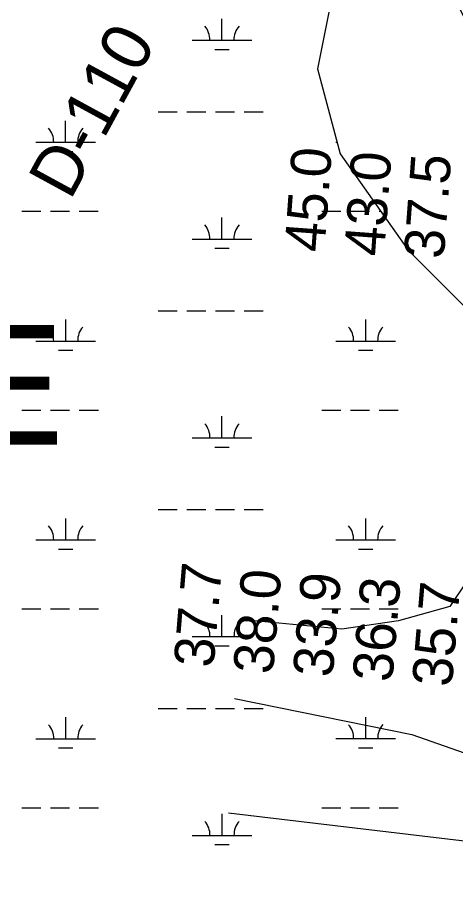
# Model space of a CAD drawing. Extents: x 3263578 to 3301413, y 764927 to 798602.
# Drawn here: x 3290176 to 3290909, y 777533 to 779010 of the extents above; entities that cross this region are included whole.
import ezdxf

# ---------------------------------------------------------------- set-up
doc = ezdxf.new("R2010")
doc.units = 0
for name, color, linetype in [('V-RIVR-RANG', 7, 'Continuous'), ('V-RIVR-RANG-IDEN', 7, 'Continuous'), ('V-TOPO-GNAM-IDEN', 7, 'Continuous'), ('V-TOPO-MAJR', 7, 'Continuous'), ('V-TOPO-MINR', 7, 'Continuous'), ('V-WETL-SWMP', 7, 'Continuous')]:
    doc.layers.add(name, color=color, linetype=linetype)

msp = doc.modelspace()

# ---------------------------------------------------------------- linework, layer by layer
at = {"layer": 'V-TOPO-MAJR'}
msp.add_lwpolyline([(3290539.3, 777870.7), (3290835.8, 777810.2), (3291117.7, 777711.5), (3291426.2, 777686.8), (3291660.5, 777667.1), (3291772.9, 777671.6), (3291863.9, 777697.6), (3291895.1, 777762.1), (3291909.7, 777831.5), (3291918.2, 777894.8), (3291915.9, 777939.1), (3291899.3, 777973.8), (3291864.7, 778024.1), (3291709.8, 778244.5), (3291488.2, 778571.5), (3291395.2, 778708.1), (3291333.2, 778772.8), (3291271.1, 778808.9), (3291211.4, 778828.1), (3291173.1, 778830.6), (3291051.2, 778850.1), (3290979.6, 778898.1), (3290910.5, 779036.2)], dxfattribs=at)
at = {"layer": 'V-TOPO-MINR'}
for points in [[(3291062.8, 778841), (3291236.5, 778807.5), (3291271.6, 778792.9), (3291357, 778721.5), (3291418.5, 778640.6), (3291640.9, 778302.8), (3291806.6, 778083.9), (3291877.6, 777988.8), (3291910.6, 777893.7), (3291886.6, 777775), (3291763.1, 777765.8), (3291520.9, 777790.1), (3291307.3, 777861.9), (3291184, 777943), (3291146.2, 778014.3), (3291070.4, 778090.5), (3290980.2, 778109.7), (3290927.9, 778067.1), (3290899.3, 778024.4), (3290813.7, 778000.9), (3290718.7, 777986.9), (3290566.7, 778001.5)], [(3291878.2, 778027.1), (3291925, 777945.9), (3291915, 777746.4), (3291838.5, 777542.4), (3291814.7, 777532.9), (3291643.7, 777533.4), (3291420.6, 777576.7), (3291064.5, 777615.5), (3290529, 777678.6)]]:
    msp.add_lwpolyline(points, dxfattribs=at)
at = {"layer": 'V-WETL-SWMP'}
for p, q in [((3290518.2, 778972.3), (3290518.2, 779008.3)), ((3290697.1, 779019.1), (3290678.1, 778924.4)), ((3290468.2, 778972.3), (3290568.2, 778972.3)), ((3290506.2, 778956.9), (3290530.2, 778956.9)), ((3290678.1, 778924.4), (3290716, 778782.2)), ((3290411.3, 778852.2), (3290443.3, 778852.2)), ((3290459.3, 778852.2), (3290491.3, 778852.2)), ((3290507.3, 778852.2), (3290539.3, 778852.2)), ((3290555.3, 778852.2), (3290587.3, 778852.2)), ((3290256.7, 778801.5), (3290256.7, 778837.5)), ((3290206.7, 778801.5), (3290306.7, 778801.5)), ((3290708.6, 778801.5), (3290710.9, 778801.5)), ((3290244.7, 778786), (3290268.7, 778786)), ((3290716, 778782.2), (3290829.6, 778621.2)), ((3290183.3, 778686), (3290215.3, 778686)), ((3290231.3, 778686), (3290263.3, 778686)), ((3290279.3, 778686), (3290311.3, 778686)), ((3290685.2, 778686.1), (3290717.2, 778686.1)), ((3290733.2, 778686.1), (3290765.2, 778686.1)), ((3290781.2, 778686.1), (3290783.8, 778686.1)), ((3290518.2, 778639.6), (3290518.2, 778675.6)), ((3290468.2, 778639.6), (3290568.2, 778639.6)), ((3290506.2, 778624.2), (3290530.2, 778624.2)), ((3290829.6, 778621.2), (3290933.7, 778517)), ((3290411.3, 778519.5), (3290443.3, 778519.5)), ((3290459.3, 778519.5), (3290491.3, 778519.5)), ((3290507.3, 778519.5), (3290539.3, 778519.6)), ((3290555.3, 778519.6), (3290587.3, 778519.6)), ((3290256.8, 778468.8), (3290256.8, 778504.8)), ((3290758.7, 778468.8), (3290758.7, 778504.8)), ((3290206.8, 778468.8), (3290306.8, 778468.8)), ((3290708.7, 778468.8), (3290808.7, 778468.8)), ((3290244.8, 778453.4), (3290268.8, 778453.4)), ((3290746.7, 778453.4), (3290770.7, 778453.4)), ((3290183.4, 778353.4), (3290215.4, 778353.4)), ((3290231.4, 778353.4), (3290263.4, 778353.4)), ((3290279.4, 778353.4), (3290311.4, 778353.4)), ((3290518.2, 778306.9), (3290518.2, 778342.9)), ((3290685.3, 778353.4), (3290717.3, 778353.4)), ((3290733.3, 778353.4), (3290765.3, 778353.4)), ((3290781.3, 778353.4), (3290813.3, 778353.4)), ((3290468.2, 778306.9), (3290568.2, 778307)), ((3290506.2, 778291.5), (3290530.2, 778291.5)), ((3290411.4, 778186.9), (3290443.4, 778186.9)), ((3290459.4, 778186.9), (3290491.4, 778186.9)), ((3290507.4, 778186.9), (3290539.4, 778186.9)), ((3290555.4, 778186.9), (3290587.4, 778186.9)), ((3290256.8, 778136.1), (3290256.8, 778172.1)), ((3290758.7, 778136.2), (3290758.7, 778172.2)), ((3290206.8, 778136.1), (3290306.8, 778136.1)), ((3290708.7, 778136.1), (3290808.7, 778136.2)), ((3290244.8, 778120.7), (3290268.8, 778120.7)), ((3290746.7, 778120.7), (3290770.7, 778120.7)), ((3290183.4, 778020.7), (3290215.4, 778020.7)), ((3290231.4, 778020.7), (3290263.4, 778020.7)), ((3290279.4, 778020.7), (3290311.4, 778020.7)), ((3290685.3, 778020.7), (3290717.3, 778020.7)), ((3290733.3, 778020.7), (3290765.3, 778020.7)), ((3290781.3, 778020.7), (3290813.3, 778020.7)), ((3290518.2, 777974.3), (3290518.2, 778010.3)), ((3290468.2, 777974.3), (3290568.2, 777974.3)), ((3290506.2, 777958.8), (3290530.2, 777958.8)), ((3290411.4, 777854.2), (3290443.4, 777854.2)), ((3290459.4, 777854.2), (3290491.4, 777854.2)), ((3290507.4, 777854.2), (3290539.4, 777854.2)), ((3290555.4, 777854.2), (3290587.4, 777854.2)), ((3290256.8, 777803.4), (3290256.8, 777839.4)), ((3290758.7, 777803.5), (3290758.7, 777839.5)), ((3290206.8, 777803.4), (3290306.8, 777803.4)), ((3290708.7, 777803.5), (3290808.7, 777803.5)), ((3290244.8, 777788), (3290268.8, 777788)), ((3290746.7, 777788), (3290770.7, 777788)), ((3290183.4, 777688), (3290215.4, 777688)), ((3290231.4, 777688), (3290263.4, 777688)), ((3290279.4, 777688), (3290311.4, 777688)), ((3290518.3, 777641.6), (3290518.3, 777677.6)), ((3290685.3, 777688), (3290717.3, 777688)), ((3290733.3, 777688), (3290765.3, 777688)), ((3290781.3, 777688), (3290813.3, 777688)), ((3290468.3, 777641.6), (3290568.3, 777641.6)), ((3290506.3, 777626.2), (3290530.3, 777626.2))]:
    msp.add_line(p, q, dxfattribs=at)
for centre, start, end in [((3290462.9, 778972.8), 359.2323, 40.776), ((3290573.4, 778972.8), 139.2323, 180.776), ((3290201.5, 778801.9), 359.2323, 40.776), ((3290312, 778801.9), 139.2323, 180.776), ((3290462.9, 778640.1), 359.2323, 40.776), ((3290573.4, 778640.1), 139.2323, 180.776), ((3290201.5, 778469.3), 359.2323, 40.776), ((3290312, 778469.3), 139.2323, 180.776), ((3290703.4, 778469.3), 359.2323, 40.776), ((3290813.9, 778469.3), 139.2323, 180.776), ((3290463, 778307.4), 359.2323, 40.776), ((3290573.4, 778307.4), 139.2323, 180.776), ((3290201.5, 778136.6), 359.2323, 40.776), ((3290312, 778136.6), 139.2323, 180.776), ((3290703.4, 778136.6), 359.2323, 40.776), ((3290813.9, 778136.6), 139.2323, 180.776), ((3290463, 777974.7), 359.2323, 40.776), ((3290573.5, 777974.8), 139.2323, 180.776), ((3290201.6, 777803.9), 359.2323, 40.776), ((3290312.1, 777803.9), 139.2323, 180.776), ((3290703.5, 777803.9), 359.2323, 40.776), ((3290814, 777804), 139.2323, 180.776), ((3290463, 777642.1), 359.2323, 40.776), ((3290573.5, 777642.1), 139.2323, 180.776)]:
    msp.add_arc(centre, 35.2, start, end, dxfattribs=at)

# ---------------------------------------------------------------- texts
at = {"layer": 'V-RIVR-RANG'}
for s, rotation, p in [('45.0', 85.7983, (3290689.5, 778616.5)), ('43.0', 85.7983, (3290789.3, 778609.5)), ('37.5', 85.7983, (3290889.3, 778605.3)), ('37.7', 85.2583, (3290504.1, 777921.2)), ('38.0', 85.2583, (3290603.5, 777910.2)), ('33.9', 85.2583, (3290703.4, 777904.9)), ('36.3', 85.2583, (3290803.1, 777897.1)), ('35.7', 85.2583, (3290902.8, 777889.1))]:
    msp.add_text(s, height=67, rotation=rotation, dxfattribs=at).set_placement(p)
at = {"layer": 'V-RIVR-RANG-IDEN'}
msp.add_text('D-110', height=83, rotation=61.4243, dxfattribs=at).set_placement((3290264.3, 778702.8))
at = {"layer": 'V-TOPO-GNAM-IDEN'}
msp.add_text('ROUGE', height=200, rotation=359.9292, dxfattribs=at).set_placement((3289273.2, 778296.7))

doc.saveas('drawing.dxf')
